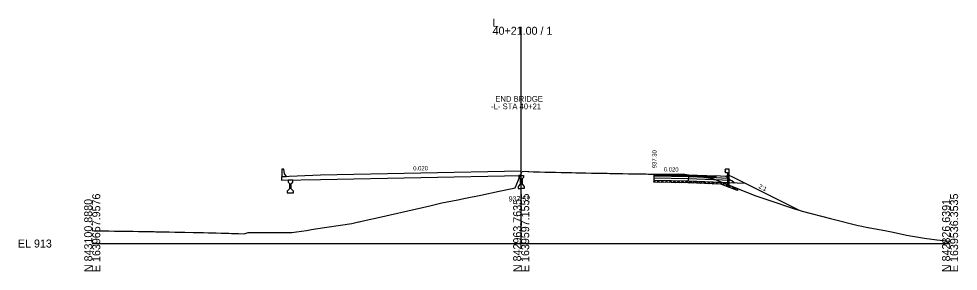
# Model space of a CAD drawing. Extents: x -26 to 1638757, y -10 to 843341.
# Drawn here: x 2324.3 to 2652.8, y -9.7 to 78.7 of the extents above; entities that cross this region are included whole.
import ezdxf

# ---------------------------------------------------------------- set-up
doc = ezdxf.new("R2010")
doc.units = 0
for name, color, linetype in [('Exist Cross Section Cell', 7, 'Continuous'), ('Exist XS Center Line Elevation Label', 7, 'Continuous'), ('Exist XS Ground Line', 7, 'Continuous'), ('Prop CMT Concrete Structures', 7, 'Continuous'), ('Prop CMT Guardrail Widen Shoulder', 7, 'Continuous'), ('Prop CMT Pvmt Course 1', 7, 'Continuous'), ('Prop CMT Pvmt Course 2', 7, 'Continuous'), ('Prop CMT Pvmt Course 3', 7, 'Continuous'), ('Prop CMT Pvmt Surface', 7, 'Continuous'), ('Prop CMT Pvmt Surface Shoulder', 7, 'Continuous'), ('Prop CMT Shld Paved Course 1', 7, 'Continuous'), ('Prop CMT Shld Paved Course 2', 7, 'Continuous'), ('Prop CMT Shld Paved Course 3', 7, 'Continuous'), ('Prop CMT Shld Paved Course 4', 7, 'Continuous'), ('Prop CMT Slope Grass', 7, 'Continuous'), ('Prop CMT Subgrade Earthwork', 7, 'Continuous'), ('Prop XS Label Text', 7, 'Continuous'), ('Prop XS SBG', 7, 'Continuous'), ('Prop XS SE Text', 7, 'Continuous'), ('Prop XS Side Slope Text', 7, 'Continuous'), ('Prop XS Undercut Exc Hatch', 7, 'Continuous')]:
    doc.layers.add(name, color=color, linetype=linetype)

msp = doc.modelspace()

# ---------------------------------------------------------------- linework, layer by layer
at = {"layer": 'Exist Cross Section Cell'}
for p, q in [((2500, 0), (2500, 75.86)), ((2350, 0), (2500, 0)), ((2500, 0), (2650, 0))]:
    msp.add_line(p, q, dxfattribs=at)
at = {"layer": 'Exist XS Ground Line'}
msp.add_lwpolyline([(2350, 4.52), (2350.65, 4.5), (2351.44, 4.49), (2352.41, 4.47), (2353.01, 4.46), (2354.27, 4.43), (2355.07, 4.41), (2355.76, 4.4), (2357.81, 4.37), (2358.6, 4.35), (2360.67, 4.32), (2363.28, 4.28), (2364.28, 4.27), (2366.18, 4.23), (2366.55, 4.23), (2368.07, 4.2), (2368.75, 4.19), (2370.5, 4.17), (2371.62, 4.16), (2372.2, 4.15), (2374.74, 4.12), (2376.15, 4.09), (2376.95, 4.09), (2378.88, 4.03), (2379.69, 4), (2380.33, 3.98), (2382.42, 3.94), (2385.24, 3.9), (2387.89, 3.83), (2388.91, 3.81), (2390.63, 3.76), (2391.22, 3.75), (2393.36, 3.7), (2395.07, 3.67), (2396.34, 3.63), (2397.81, 3.57), (2398.74, 3.53), (2399.09, 3.52), (2401.14, 3.48), (2403.14, 3.43), (2403.46, 3.54), (2404.47, 3.89), (2405.32, 3.9), (2406.34, 3.9), (2410.77, 3.89), (2411.79, 3.89), (2413.07, 3.89), (2416.84, 3.89), (2419.82, 3.89), (2421.48, 4.09), (2424.95, 4.53), (2426.64, 4.91), (2428.09, 5.09), (2440.76, 7.04), (2443.06, 7.56), (2443.4, 7.64), (2444.79, 7.93), (2451.17, 9.38), (2454.23, 10.08), (2460.37, 11.47), (2468.03, 13.24), (2469.5, 13.58), (2472.28, 14.22), (2477.84, 15.33), (2480.48, 15.87), (2485.91, 16.96), (2492.28, 18.3), (2494.02, 18.66), (2497.92, 19.49), (2499.66, 23.69), (2500, 24.52), (2500.3, 25.26), (2501.35, 25.29), (2502.33, 25.22), (2502.73, 25.2), (2504.26, 25.15), (2505.48, 25.11), (2506.38, 25.09), (2508.31, 25), (2509.18, 24.99), (2509.99, 24.97), (2510.95, 24.95), (2512.06, 24.93), (2513.96, 24.89), (2514.57, 24.88), (2515.85, 24.86), (2516.42, 24.84), (2517.75, 24.82), (2519.16, 24.79), (2520.74, 24.75), (2521.94, 24.73), (2522.58, 24.72), (2524.63, 24.68), (2525.33, 24.67), (2526.9, 24.63), (2527.36, 24.62), (2529.12, 24.59), (2530.1, 24.57), (2531.01, 24.55), (2533.13, 24.51), (2533.85, 24.5), (2534.22, 24.49), (2535.57, 24.48), (2537.55, 24.44), (2538.3, 24.43), (2539.24, 24.41), (2540.48, 24.39), (2541.04, 24.38), (2542.47, 24.36), (2543.77, 24.34), (2544.58, 24.33), (2545.48, 24.31), (2546.14, 24.31), (2546.51, 24.3), (2547.38, 24.29), (2549.24, 24.26), (2551.57, 24.26), (2552.07, 24.26), (2553.39, 24.28), (2555.04, 24.41), (2557.25, 24.32), (2562.17, 23.5), (2562.94, 23.37), (2567.03, 22.71), (2569.56, 21.74), (2581.7, 16.78), (2586.3, 15.26), (2595.98, 12.04), (2597.24, 11.64), (2598.25, 11.36), (2608.18, 8.78), (2617.91, 6.35), (2619.12, 6.05), (2619.59, 5.92), (2620.65, 5.73), (2627.17, 4.56), (2630.06, 3.95), (2634.75, 2.9), (2641, 1.89), (2645.32, 1.34), (2650, 0.83)], dxfattribs=at)
at = {"layer": 'Prop CMT Concrete Structures'}
for points in [[(2500, 25.31), (2429.79, 23.91), (2416.16, 23.36)], [(2416.16, 22.13), (2429.79, 22.41), (2500, 23.81)], [(2416.16, 23.36), (2416.16, 22.13)], [(2417.79, 23.43), (2417.79, 23.68), (2417.21, 24.45), (2417.04, 26.03), (2416.29, 26.03), (2416.29, 23.37)], [(2416.29, 23.37), (2417.79, 23.43)], [(2500, 23.81), (2499.17, 23.79)], [(2499.17, 23.79), (2499.17, 23.14)], [(2499.17, 23.14), (2499.67, 22.64)], [(2500, 23.81), (2500, 25.31)], [(2500, 23.81), (2500, 25.31)], [(2500, 23.81), (2500.83, 23.79)], [(2500.83, 23.14), (2500.33, 22.64)], [(2500.83, 23.79), (2500.83, 23.14)], [(2420.12, 22.21), (2419.29, 22.2), (2418.46, 22.18)], [(2418.46, 22.18), (2418.46, 21.53)], [(2418.46, 21.53), (2418.96, 21.03)], [(2418.96, 21.03), (2418.96, 19.11)], [(2419.62, 21.03), (2420.12, 21.53)], [(2419.62, 19.11), (2419.62, 21.03)], [(2420.12, 21.53), (2420.12, 22.21)], [(2499.67, 20.73), (2498.92, 19.98)], [(2498.92, 19.98), (2498.92, 19.31)], [(2499.67, 22.64), (2499.67, 20.73)], [(2500.33, 22.64), (2500.33, 20.73)], [(2500.33, 20.73), (2501.08, 19.98)], [(2501.08, 19.98), (2501.08, 19.31)], [(2418.96, 19.11), (2418.21, 18.36)], [(2418.21, 18.36), (2418.21, 17.7)], [(2418.21, 17.7), (2419.29, 17.7), (2420.37, 17.7)], [(2420.37, 18.36), (2419.62, 19.11)], [(2420.37, 17.7), (2420.37, 18.36)], [(2498.92, 19.31), (2500, 19.31)], [(2501.08, 19.31), (2500, 19.31)]]:
    msp.add_lwpolyline(points, dxfattribs=at)
at = {"layer": 'Prop CMT Guardrail Widen Shoulder'}
for points in [[(2572.79, 26.06), (2571.46, 26.06), (2571.19, 25.77)], [(2571.19, 25.77), (2571.46, 25.48)], [(2571.46, 25.48), (2571.19, 25.19)], [(2571.19, 25.19), (2571.46, 24.9), (2572.13, 24.9)], [(2572.13, 24.9), (2572.13, 20.06)], [(2572.79, 20.06), (2572.79, 26.06)], [(2572.13, 20.06), (2572.79, 20.06)]]:
    msp.add_lwpolyline(points, dxfattribs=at)
at = {"layer": 'Prop CMT Pvmt Course 1'}
for points in [[(2546.46, 24.3), (2558.46, 24.06)], [(2546.46, 24.05), (2546.46, 24.3)], [(2558.46, 23.81), (2546.46, 24.05)], [(2558.46, 24.06), (2558.46, 23.81)]]:
    msp.add_lwpolyline(points, dxfattribs=at)
at = {"layer": 'Prop CMT Pvmt Course 2'}
for points in [[(2546.46, 23.72), (2546.46, 24.05)], [(2546.46, 24.05), (2558.46, 23.81)], [(2558.46, 23.48), (2546.46, 23.72)]]:
    msp.add_lwpolyline(points, dxfattribs=at)
at = {"layer": 'Prop CMT Pvmt Course 3'}
for p, q in [((2546.46, 22.97), (2558.46, 22.73)), ((2558.46, 22.73), (2573.21, 22.14)), ((2572, 22.88), (2572.5, 22.86)), ((2573.21, 22.14), (2573.71, 22.11))]:
    msp.add_line(p, q, dxfattribs=at)
for points in [[(2546.46, 23.72), (2558.46, 23.48)], [(2546.46, 22.97), (2546.46, 23.72)], [(2558.46, 23.48), (2558.46, 22.73)]]:
    msp.add_lwpolyline(points, dxfattribs=at)
at = {"layer": 'Prop CMT Pvmt Surface'}
msp.add_lwpolyline([(2546.46, 24.3), (2558.46, 24.06)], dxfattribs=at)
at = {"layer": 'Prop CMT Pvmt Surface Shoulder'}
msp.add_lwpolyline([(2558.46, 24.06), (2568.13, 23.68)], dxfattribs=at)
at = {"layer": 'Prop CMT Shld Paved Course 1'}
for points in [[(2558.46, 24.06), (2568.13, 23.68)], [(2558.46, 23.81), (2558.46, 24.06)], [(2568.13, 23.43), (2558.46, 23.81)], [(2568.13, 23.68), (2568.13, 23.43)], [(2568.13, 23.68), (2568.13, 23.43)]]:
    msp.add_lwpolyline(points, dxfattribs=at)
at = {"layer": 'Prop CMT Shld Paved Course 2'}
for points in [[(2558.46, 23.81), (2568.13, 23.43)], [(2558.46, 23.48), (2558.46, 23.81)], [(2568.13, 23.09), (2558.46, 23.48)], [(2568.13, 23.43), (2568.13, 23.09)], [(2568.13, 23.43), (2568.13, 23.09)]]:
    msp.add_lwpolyline(points, dxfattribs=at)
at = {"layer": 'Prop CMT Shld Paved Course 3'}
msp.add_line((2572.5, 22.86), (2573.21, 22.14), dxfattribs=at)
msp.add_lwpolyline([(2558.46, 23.48), (2568.13, 23.09)], dxfattribs=at)
at = {"layer": 'Prop CMT Shld Paved Course 4'}
for p, q in [((2546.46, 22.14), (2558.46, 21.9)), ((2558.46, 21.9), (2574.08, 21.27)), ((2573.71, 22.11), (2574.58, 21.24))]:
    msp.add_line(p, q, dxfattribs=at)
for points in [[(2546.46, 22.14), (2546.46, 22.97)], [(2558.46, 21.9), (2558.46, 22.73)]]:
    msp.add_lwpolyline(points, dxfattribs=at)
at = {"layer": 'Prop CMT Slope Grass'}
for points in [[(2572, 23.7), (2572.62, 23.96), (2574.14, 23.2)], [(2574.14, 23.2), (2597.26, 11.64)]]:
    msp.add_lwpolyline(points, dxfattribs=at)
at = {"layer": 'Prop CMT Subgrade Earthwork'}
msp.add_line((2546.46, 22.14), (2546.46, 24.24), dxfattribs=at)
for points in [[(2546.46, 22.14), (2558.46, 21.9)], [(2558.46, 21.9), (2578.33, 21.1)]]:
    msp.add_lwpolyline(points, dxfattribs=at)
at = {"layer": 'Prop XS SBG'}
for p, q in [((2568.13, 23.09), (2572, 22.88)), ((2572, 22.88), (2572, 23.7))]:
    msp.add_line(p, q, dxfattribs=at)
msp.add_lwpolyline([(2572, 23.7), (2571.33, 23.42), (2568.13, 23.68), (2568.13, 23.09)], dxfattribs=at)
at = {"layer": 'Prop XS Undercut Exc Hatch'}
for p, q in [((2546.45, 21.47), (2546.46, 22.14)), ((2546.45, 21.74), (2546.84, 22.13)), ((2558.44, 21.23), (2546.45, 21.47)), ((2546.46, 22.14), (2558.46, 21.9)), ((2546.46, 21.91), (2546.91, 21.46)), ((2547.57, 21.44), (2548.23, 22.1)), ((2547.66, 22.11), (2548.35, 21.43)), ((2548.96, 21.42), (2549.62, 22.07)), ((2549.11, 22.08), (2549.79, 21.4)), ((2550.35, 21.39), (2551, 22.05)), ((2550.55, 22.06), (2551.23, 21.37)), ((2551.73, 21.36), (2552.39, 22.02)), ((2551.99, 22.03), (2552.68, 21.34)), ((2553.12, 21.33), (2553.78, 21.99)), ((2553.44, 22), (2554.12, 21.31)), ((2554.51, 21.31), (2555.16, 21.96)), ((2554.88, 21.97), (2555.56, 21.28)), ((2555.89, 21.28), (2556.55, 21.94)), ((2556.32, 21.94), (2557.01, 21.26)), ((2557.28, 21.25), (2557.94, 21.91)), ((2557.77, 21.91), (2558.45, 21.23)), ((2569.83, 20.77), (2558.44, 21.23)), ((2558.46, 21.9), (2570.01, 21.42)), ((2558.66, 21.22), (2559.3, 21.86)), ((2559.23, 21.87), (2559.92, 21.17)), ((2560.02, 21.16), (2560.66, 21.81)), ((2560.7, 21.81), (2561.4, 21.11)), ((2561.38, 21.11), (2562.02, 21.75)), ((2562.18, 21.74), (2562.87, 21.05)), ((2562.74, 21.06), (2563.38, 21.69)), ((2563.65, 21.68), (2564.34, 20.99)), ((2564.1, 21), (2564.74, 21.64)), ((2565.13, 21.62), (2565.82, 20.93)), ((2565.46, 20.95), (2566.1, 21.58)), ((2566.6, 21.56), (2567.29, 20.87)), ((2566.82, 20.89), (2567.45, 21.53)), ((2568.07, 21.5), (2568.76, 20.81)), ((2568.18, 20.84), (2568.81, 21.47)), ((2569.54, 20.78), (2570.13, 21.38)), ((2569.55, 21.44), (2570.45, 20.54)), ((2570.01, 21.42), (2575.6, 19.31)), ((2570.64, 20.47), (2571.16, 20.99)), ((2571.58, 20.83), (2572.33, 20.08)), ((2571.66, 20.08), (2572.18, 20.6)), ((2572.33, 20.08), (2572.72, 19.68)), ((2572.69, 19.69), (2573.21, 20.21)), ((2573.72, 19.31), (2574.23, 19.82)), ((2573.85, 19.97), (2575, 18.82)), ((2574.75, 18.92), (2575.26, 19.43)), ((2575.6, 19.31), (2575.6, 18.6))]:
    msp.add_line(p, q, dxfattribs=at)
msp.add_lwpolyline([(2575.6, 18.6), (2569.83, 20.77)], dxfattribs=at)

# ---------------------------------------------------------------- texts
at = {"layer": 'Exist Cross Section Cell'}
for s, p in [('40+21.00 / 1', (2490, 73.06)), ('L', (2490, 75.86)), ('EL 913', (2324, -1.4))]:
    msp.add_text(s, height=2.8, dxfattribs=at).set_placement(p)
for s, p in [('E 1639657.9576', (2352.8, -10)), ('E 1639597.1555', (2502.8, -10)), ('E 1639536.3535', (2652.8, -10)), ('N 843100.8880', (2350, -10)), ('N 842963.7635', (2500, -10)), ('N 842826.6391', (2650, -10))]:
    msp.add_text(s, height=2.8, rotation=90, dxfattribs=at).set_placement(p)
at = {"layer": 'Exist XS Center Line Elevation Label'}
msp.add_text('937.52', height=1.8, dxfattribs=at).set_placement((2495.61, 14.72))
at = {"layer": 'Prop XS Label Text'}
for s, p in [('END BRIDGE', (2490.96, 49.62)), ('-L- STA 40+21', (2489.49, 47))]:
    msp.add_text(s, height=2, dxfattribs=at).set_placement(p)
at = {"layer": 'Prop XS SE Text'}
for s, rotation, p in [('937.30', 89.6864, (2547.31, 26.35)), ('0.020', 1.1456, (2462.25, 25.55)), ('0.020', 358.8543, (2549.86, 25.24))]:
    msp.add_text(s, height=1.5, rotation=rotation, dxfattribs=at).set_placement(p)
at = {"layer": 'Prop XS Side Slope Text'}
msp.add_text('2:1', height=1.5, rotation=333.4351, dxfattribs=at).set_placement((2582.89, 19.54))

doc.saveas('drawing.dxf')
